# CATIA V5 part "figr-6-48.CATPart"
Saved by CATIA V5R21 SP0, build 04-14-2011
Part number: Part1
Bounding box of the stored display mesh (mm): x -54.76 to 54.76, y -32.885 to 32.885, z 0 to 59
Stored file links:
  D:\CATIA V5R21 E-RESOURCES\CATIA-V5R21\catia-v5r21-prt\c06-catia-v5r21-prt\c06-catia-v5r21-figr-6-48.CATPart
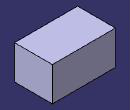
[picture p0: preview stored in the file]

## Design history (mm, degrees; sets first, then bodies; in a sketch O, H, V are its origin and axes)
Body1 (main body)
  Sketch1 on xy-plane, origin (0, 0, 0), H (1, 0, 0), V (0, 1, 0)
    line L1 (-54.7599, 32.8853) -> (54.7599, 32.8853)
    line L2 (54.7599, 32.8853) -> (54.7599, -32.8853)
    line L3 (54.7599, -32.8853) -> (-54.7599, -32.8853)
    line L4 (-54.7599, -32.8853) -> (-54.7599, 32.8853)
    axis line L5 (54.7599, -32.8853) -> (-54.7599, 32.8853)
    horizontal: L1 H, L3 H
    vertical: L2 V, L4 V
    midpoint: O L5
  Pad1: profile Sketch1, direction (0, 0, 1), length 59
